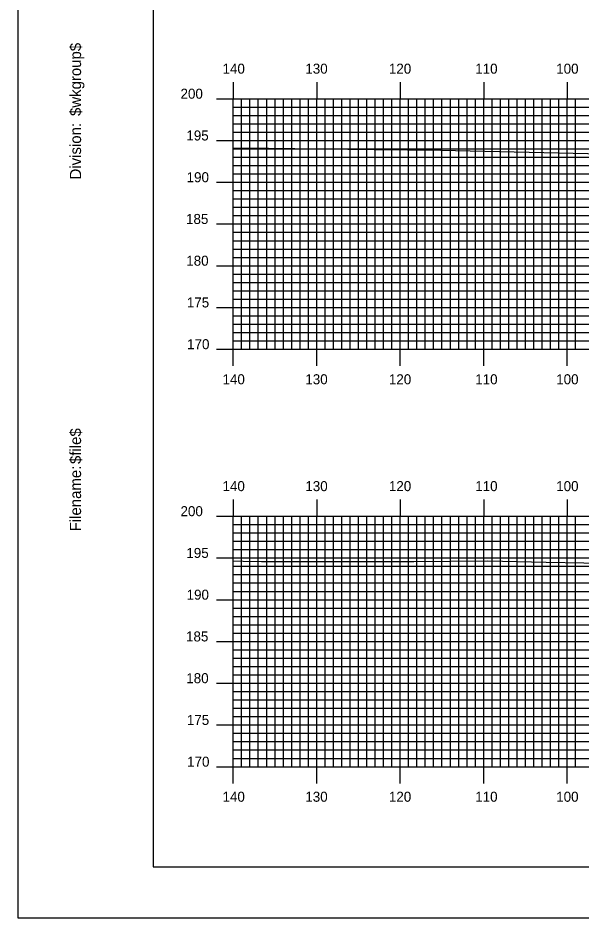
# Model space of a CAD drawing. Extents: x 1797207 to 1797550, y 442591 to 442811.
# Drawn here: x 1797207.1 to 1797274.6, y 442590.5 to 442698.3 of the extents above; entities that cross this region are included whole.
import ezdxf

# ---------------------------------------------------------------- set-up
doc = ezdxf.new("R2010")
doc.units = 0
for name, color, linetype in [('BORDER', 7, 'Continuous'), ('H_V ANNOTATION', 7, 'Continuous'), ('MAJOR', 7, 'Continuous'), ('MINOR', 7, 'Continuous'), ('PLOT BOUNDARY', 7, 'Continuous'), ('S_Roadway_Centerline', 7, 'Continuous')]:
    doc.layers.add(name, color=color, linetype=linetype)

msp = doc.modelspace()

# ---------------------------------------------------------------- linework, layer by layer
at = {"layer": 'BORDER'}
msp.add_lwpolyline([(1797223.33, 442596.67), (1797543.33, 442596.67), (1797543.33, 442806.67), (1797223.33, 442806.67)], close=True, dxfattribs=at)
at = {"layer": 'MAJOR'}
for p, q in [((1797232.93, 442690.67), (1797232.93, 442688.67)), ((1797242.93, 442690.67), (1797242.93, 442688.67)), ((1797252.93, 442690.67), (1797252.93, 442688.67)), ((1797262.93, 442690.67), (1797262.93, 442688.67)), ((1797272.93, 442690.67), (1797272.93, 442688.67)), ((1797230.93, 442688.67), (1797232.93, 442688.67)), ((1797232.93, 442688.67), (1797512.93, 442688.67)), ((1797232.93, 442658.67), (1797232.93, 442688.67)), ((1797232.93, 442658.67), (1797232.93, 442688.67)), ((1797232.93, 442688.67), (1797512.93, 442688.67)), ((1797242.93, 442658.67), (1797242.93, 442688.67)), ((1797252.93, 442658.67), (1797252.93, 442688.67)), ((1797262.93, 442658.67), (1797262.93, 442688.67)), ((1797272.93, 442658.67), (1797272.93, 442688.67)), ((1797230.93, 442683.67), (1797232.93, 442683.67)), ((1797232.93, 442683.67), (1797512.93, 442683.67)), ((1797230.93, 442678.67), (1797232.93, 442678.67)), ((1797232.93, 442678.67), (1797512.93, 442678.67)), ((1797230.93, 442673.67), (1797232.93, 442673.67)), ((1797232.93, 442673.67), (1797512.93, 442673.67)), ((1797230.93, 442668.67), (1797232.93, 442668.67)), ((1797232.93, 442668.67), (1797512.93, 442668.67)), ((1797230.93, 442663.67), (1797232.93, 442663.67)), ((1797232.93, 442663.67), (1797512.93, 442663.67)), ((1797230.93, 442658.67), (1797232.93, 442658.67)), ((1797232.93, 442658.67), (1797512.93, 442658.67)), ((1797232.93, 442658.67), (1797512.93, 442658.67)), ((1797232.93, 442656.66), (1797232.93, 442658.67)), ((1797242.93, 442656.66), (1797242.93, 442658.67)), ((1797252.93, 442656.66), (1797252.93, 442658.67)), ((1797262.93, 442656.66), (1797262.93, 442658.67)), ((1797272.93, 442656.66), (1797272.93, 442658.67)), ((1797232.93, 442640.67), (1797232.93, 442638.67)), ((1797242.93, 442640.67), (1797242.93, 442638.67)), ((1797252.93, 442640.67), (1797252.93, 442638.67)), ((1797262.93, 442640.67), (1797262.93, 442638.67)), ((1797272.93, 442640.67), (1797272.93, 442638.67)), ((1797230.93, 442638.67), (1797232.93, 442638.67)), ((1797232.93, 442638.67), (1797512.93, 442638.67)), ((1797232.93, 442608.67), (1797232.93, 442638.67)), ((1797232.93, 442608.67), (1797232.93, 442638.67)), ((1797232.93, 442638.67), (1797512.93, 442638.67)), ((1797242.93, 442608.67), (1797242.93, 442638.67)), ((1797252.93, 442608.67), (1797252.93, 442638.67)), ((1797262.93, 442608.67), (1797262.93, 442638.67)), ((1797272.93, 442608.67), (1797272.93, 442638.67)), ((1797230.93, 442633.67), (1797232.93, 442633.67)), ((1797232.93, 442633.67), (1797512.93, 442633.67)), ((1797230.93, 442628.67), (1797232.93, 442628.67)), ((1797232.93, 442628.67), (1797512.93, 442628.67)), ((1797230.93, 442623.67), (1797232.93, 442623.67)), ((1797232.93, 442623.67), (1797512.93, 442623.67)), ((1797230.93, 442618.67), (1797232.93, 442618.67)), ((1797232.93, 442618.67), (1797512.93, 442618.67)), ((1797230.93, 442613.67), (1797232.93, 442613.67)), ((1797232.93, 442613.67), (1797512.93, 442613.67)), ((1797230.93, 442608.67), (1797232.93, 442608.67)), ((1797232.93, 442608.67), (1797512.93, 442608.67)), ((1797232.93, 442608.67), (1797512.93, 442608.67)), ((1797232.93, 442606.66), (1797232.93, 442608.67)), ((1797242.93, 442606.66), (1797242.93, 442608.67)), ((1797252.93, 442606.66), (1797252.93, 442608.67)), ((1797262.93, 442606.66), (1797262.93, 442608.67)), ((1797272.93, 442606.66), (1797272.93, 442608.67))]:
    msp.add_line(p, q, dxfattribs=at)
at = {"layer": 'MINOR'}
for p, q in [((1797233.93, 442658.67), (1797233.93, 442688.67)), ((1797234.93, 442658.67), (1797234.93, 442688.67)), ((1797235.93, 442658.67), (1797235.93, 442688.67)), ((1797236.93, 442658.67), (1797236.93, 442688.67)), ((1797237.93, 442658.67), (1797237.93, 442688.67)), ((1797238.93, 442658.67), (1797238.93, 442688.67)), ((1797239.93, 442658.67), (1797239.93, 442688.67)), ((1797240.93, 442658.67), (1797240.93, 442688.67)), ((1797241.93, 442658.67), (1797241.93, 442688.67)), ((1797243.93, 442658.67), (1797243.93, 442688.67)), ((1797244.93, 442658.67), (1797244.93, 442688.67)), ((1797245.93, 442658.67), (1797245.93, 442688.67)), ((1797246.93, 442658.67), (1797246.93, 442688.67)), ((1797247.93, 442658.67), (1797247.93, 442688.67)), ((1797248.93, 442658.67), (1797248.93, 442688.67)), ((1797249.93, 442658.67), (1797249.93, 442688.67)), ((1797250.93, 442658.67), (1797250.93, 442688.67)), ((1797251.93, 442658.67), (1797251.93, 442688.67)), ((1797253.93, 442658.67), (1797253.93, 442688.67)), ((1797254.93, 442658.67), (1797254.93, 442688.67)), ((1797255.93, 442658.67), (1797255.93, 442688.67)), ((1797256.93, 442658.67), (1797256.93, 442688.67)), ((1797257.93, 442658.67), (1797257.93, 442688.67)), ((1797258.93, 442658.67), (1797258.93, 442688.67)), ((1797259.93, 442658.67), (1797259.93, 442688.67)), ((1797260.93, 442658.67), (1797260.93, 442688.67)), ((1797261.93, 442658.67), (1797261.93, 442688.67)), ((1797263.93, 442658.67), (1797263.93, 442688.67)), ((1797264.93, 442658.67), (1797264.93, 442688.67)), ((1797265.93, 442658.67), (1797265.93, 442688.67)), ((1797266.93, 442658.67), (1797266.93, 442688.67)), ((1797267.93, 442658.67), (1797267.93, 442688.67)), ((1797268.93, 442658.67), (1797268.93, 442688.67)), ((1797269.93, 442658.67), (1797269.93, 442688.67)), ((1797270.93, 442658.67), (1797270.93, 442688.67)), ((1797271.93, 442658.67), (1797271.93, 442688.67)), ((1797273.93, 442658.67), (1797273.93, 442688.67)), ((1797232.93, 442687.67), (1797512.93, 442687.67)), ((1797232.93, 442687.67), (1797234.94, 442687.67)), ((1797232.93, 442686.67), (1797512.93, 442686.67)), ((1797232.93, 442686.67), (1797234.94, 442686.67)), ((1797232.93, 442685.67), (1797512.93, 442685.67)), ((1797232.93, 442685.67), (1797234.94, 442685.67)), ((1797232.93, 442684.67), (1797512.93, 442684.67)), ((1797232.93, 442684.67), (1797234.94, 442684.67)), ((1797232.93, 442682.67), (1797512.93, 442682.67)), ((1797232.93, 442682.67), (1797234.94, 442682.67)), ((1797232.93, 442681.67), (1797512.93, 442681.67)), ((1797232.93, 442681.67), (1797234.94, 442681.67)), ((1797232.93, 442680.67), (1797512.93, 442680.67)), ((1797232.93, 442680.67), (1797234.94, 442680.67)), ((1797232.93, 442679.67), (1797512.93, 442679.67)), ((1797232.93, 442679.67), (1797234.94, 442679.67)), ((1797232.93, 442677.67), (1797512.93, 442677.67)), ((1797232.93, 442677.67), (1797234.94, 442677.67)), ((1797232.93, 442676.67), (1797512.93, 442676.67)), ((1797232.93, 442676.67), (1797234.94, 442676.67)), ((1797232.93, 442675.67), (1797512.93, 442675.67)), ((1797232.93, 442675.67), (1797234.94, 442675.67)), ((1797232.93, 442674.67), (1797512.93, 442674.67)), ((1797232.93, 442674.67), (1797234.94, 442674.67)), ((1797232.93, 442672.67), (1797512.93, 442672.67)), ((1797232.93, 442672.67), (1797234.94, 442672.67)), ((1797232.93, 442671.67), (1797512.93, 442671.67)), ((1797232.93, 442671.67), (1797234.94, 442671.67)), ((1797232.93, 442670.67), (1797512.93, 442670.67)), ((1797232.93, 442670.67), (1797234.94, 442670.67)), ((1797232.93, 442669.67), (1797512.93, 442669.67)), ((1797232.93, 442669.67), (1797234.94, 442669.67)), ((1797232.93, 442667.67), (1797512.93, 442667.67)), ((1797232.93, 442667.67), (1797234.94, 442667.67)), ((1797232.93, 442666.67), (1797512.93, 442666.67)), ((1797232.93, 442666.67), (1797234.94, 442666.67)), ((1797232.93, 442665.67), (1797512.93, 442665.67)), ((1797232.93, 442665.67), (1797234.94, 442665.67)), ((1797232.93, 442664.67), (1797512.93, 442664.67)), ((1797232.93, 442664.67), (1797234.94, 442664.67)), ((1797232.93, 442662.67), (1797512.93, 442662.67)), ((1797232.93, 442662.67), (1797234.94, 442662.67)), ((1797232.93, 442661.67), (1797512.93, 442661.67)), ((1797232.93, 442661.67), (1797234.94, 442661.67)), ((1797232.93, 442660.67), (1797512.93, 442660.67)), ((1797232.93, 442660.67), (1797234.94, 442660.67)), ((1797232.93, 442659.67), (1797512.93, 442659.67)), ((1797232.93, 442659.67), (1797234.94, 442659.67)), ((1797233.93, 442608.67), (1797233.93, 442638.67)), ((1797234.93, 442608.67), (1797234.93, 442638.67)), ((1797235.93, 442608.67), (1797235.93, 442638.67)), ((1797236.93, 442608.67), (1797236.93, 442638.67)), ((1797237.93, 442608.67), (1797237.93, 442638.67)), ((1797238.93, 442608.67), (1797238.93, 442638.67)), ((1797239.93, 442608.67), (1797239.93, 442638.67)), ((1797240.93, 442608.67), (1797240.93, 442638.67)), ((1797241.93, 442608.67), (1797241.93, 442638.67)), ((1797243.93, 442608.67), (1797243.93, 442638.67)), ((1797244.93, 442608.67), (1797244.93, 442638.67)), ((1797245.93, 442608.67), (1797245.93, 442638.67)), ((1797246.93, 442608.67), (1797246.93, 442638.67)), ((1797247.93, 442608.67), (1797247.93, 442638.67)), ((1797248.93, 442608.67), (1797248.93, 442638.67)), ((1797249.93, 442608.67), (1797249.93, 442638.67)), ((1797250.93, 442608.67), (1797250.93, 442638.67)), ((1797251.93, 442608.67), (1797251.93, 442638.67)), ((1797253.93, 442608.67), (1797253.93, 442638.67)), ((1797254.93, 442608.67), (1797254.93, 442638.67)), ((1797255.93, 442608.67), (1797255.93, 442638.67)), ((1797256.93, 442608.67), (1797256.93, 442638.67)), ((1797257.93, 442608.67), (1797257.93, 442638.67)), ((1797258.93, 442608.67), (1797258.93, 442638.67)), ((1797259.93, 442608.67), (1797259.93, 442638.67)), ((1797260.93, 442608.67), (1797260.93, 442638.67)), ((1797261.93, 442608.67), (1797261.93, 442638.67)), ((1797263.93, 442608.67), (1797263.93, 442638.67)), ((1797264.93, 442608.67), (1797264.93, 442638.67)), ((1797265.93, 442608.67), (1797265.93, 442638.67)), ((1797266.93, 442608.67), (1797266.93, 442638.67)), ((1797267.93, 442608.67), (1797267.93, 442638.67)), ((1797268.93, 442608.67), (1797268.93, 442638.67)), ((1797269.93, 442608.67), (1797269.93, 442638.67)), ((1797270.93, 442608.67), (1797270.93, 442638.67)), ((1797271.93, 442608.67), (1797271.93, 442638.67)), ((1797273.93, 442608.67), (1797273.93, 442638.67)), ((1797232.93, 442637.67), (1797512.93, 442637.67)), ((1797232.93, 442637.67), (1797234.94, 442637.67)), ((1797232.93, 442636.67), (1797512.93, 442636.67)), ((1797232.93, 442636.67), (1797234.94, 442636.67)), ((1797232.93, 442635.67), (1797512.93, 442635.67)), ((1797232.93, 442635.67), (1797234.94, 442635.67)), ((1797232.93, 442634.67), (1797512.93, 442634.67)), ((1797232.93, 442634.67), (1797234.94, 442634.67)), ((1797232.93, 442632.67), (1797512.93, 442632.67)), ((1797232.93, 442632.67), (1797234.94, 442632.67)), ((1797232.93, 442631.67), (1797512.93, 442631.67)), ((1797232.93, 442631.67), (1797234.94, 442631.67)), ((1797232.93, 442630.67), (1797512.93, 442630.67)), ((1797232.93, 442630.67), (1797234.94, 442630.67)), ((1797232.93, 442629.67), (1797512.93, 442629.67)), ((1797232.93, 442629.67), (1797234.94, 442629.67)), ((1797232.93, 442627.67), (1797512.93, 442627.67)), ((1797232.93, 442627.67), (1797234.94, 442627.67)), ((1797232.93, 442626.67), (1797512.93, 442626.67)), ((1797232.93, 442626.67), (1797234.94, 442626.67)), ((1797232.93, 442625.67), (1797512.93, 442625.67)), ((1797232.93, 442625.67), (1797234.94, 442625.67)), ((1797232.93, 442624.67), (1797512.93, 442624.67)), ((1797232.93, 442624.67), (1797234.94, 442624.67)), ((1797232.93, 442622.67), (1797512.93, 442622.67)), ((1797232.93, 442622.67), (1797234.94, 442622.67)), ((1797232.93, 442621.67), (1797512.93, 442621.67)), ((1797232.93, 442621.67), (1797234.94, 442621.67)), ((1797232.93, 442620.67), (1797512.93, 442620.67)), ((1797232.93, 442620.67), (1797234.94, 442620.67)), ((1797232.93, 442619.67), (1797512.93, 442619.67)), ((1797232.93, 442619.67), (1797234.94, 442619.67)), ((1797232.93, 442617.67), (1797512.93, 442617.67)), ((1797232.93, 442617.67), (1797234.94, 442617.67)), ((1797232.93, 442616.67), (1797512.93, 442616.67)), ((1797232.93, 442616.67), (1797234.94, 442616.67)), ((1797232.93, 442615.67), (1797512.93, 442615.67)), ((1797232.93, 442615.67), (1797234.94, 442615.67)), ((1797232.93, 442614.67), (1797512.93, 442614.67)), ((1797232.93, 442614.67), (1797234.94, 442614.67)), ((1797232.93, 442612.67), (1797512.93, 442612.67)), ((1797232.93, 442612.67), (1797234.94, 442612.67)), ((1797232.93, 442611.67), (1797512.93, 442611.67)), ((1797232.93, 442611.67), (1797234.94, 442611.67)), ((1797232.93, 442610.67), (1797512.93, 442610.67)), ((1797232.93, 442610.67), (1797234.94, 442610.67)), ((1797232.93, 442609.67), (1797512.93, 442609.67)), ((1797232.93, 442609.67), (1797234.94, 442609.67))]:
    msp.add_line(p, q, dxfattribs=at)
at = {"layer": 'PLOT BOUNDARY'}
msp.add_lwpolyline([(1797207.14, 442590.55), (1797547.14, 442590.55), (1797547.14, 442810.55), (1797207.14, 442810.55)], close=True, dxfattribs=at)
at = {"layer": 'S_Roadway_Centerline'}
for points in [[(1797232.93, 442682.78), (1797237.14, 442682.75), (1797249.82, 442682.58), (1797257.81, 442682.5), (1797277.16, 442682.06), (1797278.41, 442682.05), (1797281.96, 442682.02), (1797298.75, 442681.88), (1797304.88, 442681.87), (1797318.6, 442681.48), (1797323.86, 442681.23), (1797331.88, 442680.97), (1797354, 442680.91)], [(1797232.93, 442633.32), (1797234.1, 442633.3), (1797236.32, 442633.26), (1797254.57, 442633.26), (1797263.43, 442633.34), (1797270.41, 442633.18), (1797274.92, 442633.08), (1797281.92, 442632.85), (1797291.92, 442632.83), (1797293.77, 442632.85), (1797295.12, 442632.87), (1797305.54, 442632.83), (1797315.71, 442632.64), (1797319.65, 442632.6), (1797335.82, 442632.12), (1797340.53, 442631.94), (1797346.87, 442631.81)]]:
    msp.add_lwpolyline(points, dxfattribs=at)

# ---------------------------------------------------------------- texts
at = {"layer": 'BORDER'}
for s, p in [('$wkgroup$', (1797214.7, 442686.6)), ('Division:', (1797214.7, 442679)), ('$file$', (1797214.7, 442644.92)), ('Filename:', (1797214.7, 442636.86))]:
    msp.add_text(s, height=1.339, rotation=90, dxfattribs=at).set_placement(p)
at = {"layer": 'H_V ANNOTATION'}
for s, p in [('140', (1797231.64, 442691.67)), ('130', (1797241.56, 442691.67)), ('120', (1797251.57, 442691.67)), ('110', (1797261.91, 442691.67)), ('100', (1797271.61, 442691.67)), ('200', (1797226.61, 442688.67)), ('195', (1797227.31, 442683.67)), ('190', (1797227.34, 442678.67)), ('185', (1797227.27, 442673.67)), ('180', (1797227.3, 442668.67)), ('175', (1797227.37, 442663.67)), ('170', (1797227.4, 442658.67)), ('140', (1797231.64, 442654.47)), ('130', (1797241.56, 442654.47)), ('120', (1797251.57, 442654.47)), ('110', (1797261.91, 442654.47)), ('100', (1797271.61, 442654.47)), ('140', (1797231.64, 442641.67)), ('130', (1797241.56, 442641.67)), ('120', (1797251.57, 442641.67)), ('110', (1797261.91, 442641.67)), ('100', (1797271.61, 442641.67)), ('200', (1797226.61, 442638.67)), ('195', (1797227.31, 442633.67)), ('190', (1797227.34, 442628.67)), ('185', (1797227.27, 442623.67)), ('180', (1797227.3, 442618.67)), ('175', (1797227.37, 442613.67)), ('170', (1797227.4, 442608.67)), ('140', (1797231.64, 442604.47)), ('130', (1797241.56, 442604.47)), ('120', (1797251.57, 442604.47)), ('110', (1797261.91, 442604.47)), ('100', (1797271.61, 442604.47))]:
    msp.add_text(s, height=1.2, dxfattribs=at).set_placement(p)
at = {"layer": 'MAJOR'}
for p in [(1797232.92, 442658.67), (1797232.92, 442608.67)]:
    msp.add_text('-', height=0.012, dxfattribs=at).set_placement(p)

doc.saveas('drawing.dxf')
